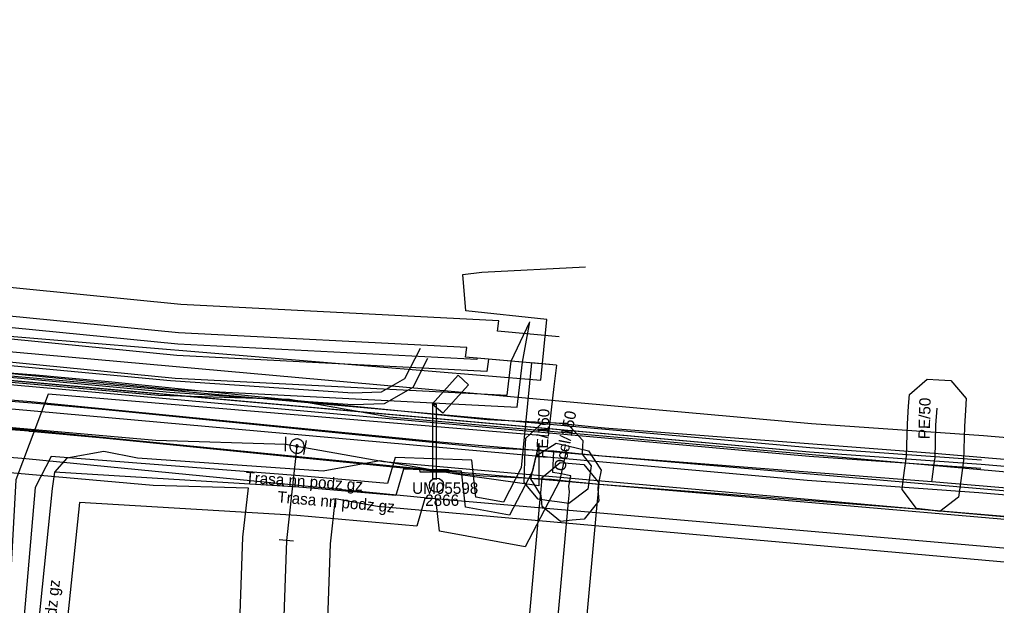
# Model space of a CAD drawing. Extents: x -762993 to -761845, y -975230 to -974501.
# Drawn here: x -762212.37 to -762178.08, y -975004.4 to -974983.83 of the extents above; entities that cross this region are included whole.
import ezdxf

# ---------------------------------------------------------------- set-up
doc = ezdxf.new("R2010")
doc.units = 0
for name, color, linetype in [('IS_CETIN_chranicka', 7, 'Continuous'), ('IS_CETIN_OP', 7, 'Continuous'), ('IS_CETIN_podzem optika zam', 7, 'Continuous'), ('IS_CEZ-D_anotace', 7, 'Continuous'), ('IS_CEZ-D_el vedeni NN podzem', 7, 'Continuous'), ('IS_CEZ-D_el vedeni VN podzem', 7, 'Continuous'), ('IS_CEZ-D_el vedeni VN podzem soubeh investice', 7, 'Continuous'), ('IS_CEZ-D_OP', 7, 'Continuous'), ('IS_CRA_podzem telekomunikace', 7, 'Continuous'), ('IS_DPmUL_OP', 7, 'Continuous'), ('IS_DPmUL_trakce anotace', 7, 'Continuous'), ('IS_DPmUL_trakce stozary', 7, 'Continuous'), ('IS_DPmUL_VO lampy', 7, 'Continuous'), ('IS_DPmUL_VO lampy anotace', 7, 'Continuous'), ('IS_DPmUL_VO vedeni podzem', 7, 'Continuous'), ('IS_GASNET_plyn NTL anotace', 7, 'Continuous'), ('IS_GASNET_plyn NTL pripojky', 7, 'Continuous'), ('IS_GASNET_plyn NTL rad', 7, 'Continuous'), ('IS_GASNET_plyn OP', 7, 'Continuous'), ('IS_SCVK_vodovod OP', 7, 'Continuous'), ('IS_SCVK_vodovod privadec', 7, 'Continuous'), ('IS_SCVK_vodovod znaky', 7, 'Continuous'), ('IS_TPS_podzem metalika', 7, 'Continuous')]:
    doc.layers.add(name, color=color, linetype=linetype)

msp = doc.modelspace()

# ---------------------------------------------------------------- linework, layer by layer
at = {"layer": 'IS_CETIN_chranicka'}
for points in [[(-762237.218, -974994.31), (-762217.891, -974995.882), (-762216.077, -974996.031), (-762184.637, -974998.851)], [(-762237.242, -974994.61), (-762217.915, -974996.182), (-762216.103, -974996.329), (-762184.663, -974999.149)], [(-762184.639, -974998.85), (-762178.609, -974999.28)], [(-762184.661, -974999.15), (-762178.631, -974999.58)]]:
    msp.add_lwpolyline(points, dxfattribs=at)
at = {"layer": 'IS_CETIN_OP'}
for points in [[(-762217.822, -974995.035), (-762216.005, -974995.184), (-762184.57, -974998.003), (-762178.542, -974998.433), (-762152.471, -975000.654), (-762131.203, -975002.624), (-762124.809, -975003.153), (-762118.93, -975003.623), (-762113.193, -975004.083), (-762107.364, -975004.514), (-762100.398, -975005.204), (-762087.589, -975006.295)], [(-762217.984, -974997.029), (-762216.175, -974997.176), (-762184.73, -974999.997), (-762178.698, -975000.427), (-762152.649, -975002.646), (-762131.377, -975004.616), (-762124.971, -975005.147), (-762119.09, -975005.617), (-762113.347, -975006.077), (-762107.536, -975006.506), (-762100.582, -975007.196), (-762087.759, -975008.287)]]:
    msp.add_lwpolyline(points, dxfattribs=at)
at = {"layer": 'IS_CETIN_podzem optika zam'}
msp.add_lwpolyline([(-762217.903, -974996.032), (-762216.09, -974996.18), (-762184.65, -974999), (-762178.62, -974999.43), (-762152.56, -975001.65), (-762131.29, -975003.62), (-762124.89, -975004.15), (-762119.01, -975004.62), (-762113.27, -975005.08), (-762107.45, -975005.51), (-762100.49, -975006.2), (-762087.674, -975007.291)], dxfattribs=at)
at = {"layer": 'IS_CEZ-D_el vedeni NN podzem'}
for points in [[(-762193.524, -974995.955), (-762195.916, -974995.748), (-762195.968, -974996.181), (-762206.85, -974995.622), (-762221.698, -974994.154), (-762246.209, -974992.883), (-762248.603, -974989.634), (-762249.046, -974987.054), (-762248.934, -974986.091), (-762247.847, -974984.536), (-762246.114, -974982.893)], [(-762193.524, -974995.955), (-762196.315, -974995.713), (-762196.321, -974995.763), (-762206.82, -974995.223), (-762221.661, -974993.755), (-762245.947, -974992.564), (-762248.224, -974989.473), (-762248.642, -974987.043), (-762248.543, -974986.191), (-762247.498, -974984.757), (-762245.839, -974983.184), (-762245.485, -974982.848), (-762245.111, -974983.239), (-762244.564, -974983.81), (-762244.131, -974983.395)], [(-762193.524, -974995.955), (-762196.714, -974995.678), (-762196.674, -974995.344), (-762206.79, -974994.824), (-762221.625, -974993.357), (-762245.684, -974992.246), (-762247.846, -974989.312), (-762248.238, -974987.032), (-762248.152, -974986.29), (-762247.149, -974984.977), (-762245.644, -974983.55), (-762245.499, -974983.413), (-762245.127, -974983.801), (-762244.853, -974984.087), (-762244.131, -974983.395)], [(-762193.524, -974995.956), (-762193.614, -974996.71), (-762193.822, -974998.453), (-762211.362, -974996.973), (-762212.503, -974999.99), (-762212.93, -975007.897), (-762212.59, -975008.699), (-762208.023, -975009.002), (-762208.841, -975020.191), (-762208.871, -975020.599), (-762216.194, -975020.151), (-762233.978, -975019.299), (-762252.877, -975017.917), (-762257.832, -975017.547), (-762262.774, -975017.178), (-762264.709, -975017.162), (-762266.642, -975017.146), (-762269.935, -975017.363)], [(-762193.524, -974995.955), (-762194.408, -974995.878), (-762194.761, -974999.565), (-762195.389, -975000.774), (-762196.355, -975000.599), (-762196.501, -974999.292), (-762199.187, -974999.2), (-762199.452, -975000.113), (-762202.537, -974999.841), (-762211.266, -974999.16), (-762211.822, -975000.258), (-762212.529, -975008.421)], [(-762194.15, -974998.7), (-762194.37, -974999.68), (-762195.17, -975001.22), (-762196.72, -975000.94), (-762196.86, -974999.68), (-762198.89, -974999.61), (-762199.16, -975000.54), (-762202.57, -975000.24), (-762211.14, -974999.72)], [(-762194.15, -974998.7), (-762194.15, -975000.19), (-762197.06, -974999.79), (-762199.73, -974999.32), (-762201.72, -974999.68), (-762208.23, -974999.23), (-762209.41, -974998.99), (-762210.71, -974999.22), (-762211.14, -974999.72)], [(-762211.14, -974999.72), (-762211.22, -975000.29), (-762212.06, -975008.46), (-762212.15, -975008.94), (-762212.14, -975010.58)]]:
    msp.add_lwpolyline(points, dxfattribs=at)
at = {"layer": 'IS_CEZ-D_el vedeni VN podzem'}
for points in [[(-762269.579, -974969.967), (-762269.216, -974971.463), (-762268.263, -974975.531), (-762267.512, -974976.705), (-762264.757, -974978.053), (-762262.777, -974978.189), (-762259.951, -974977.791), (-762257.059, -974975.091), (-762254.069, -974975.768), (-762249.558, -974980.329), (-762249.105, -974980.676), (-762247.006, -974982.026), (-762245.904, -974982.859), (-762247.37, -974986.49), (-762247.43, -974987.01), (-762247.09, -974988.99), (-762245.16, -974991.61), (-762241.64, -974993.28), (-762221.77, -974994.95), (-762206.91, -974996.42), (-762195.262, -974997.018), (-762195.119, -974995.819), (-762194.458, -974994.436)], [(-762269.605, -974971.556), (-762268.637, -974975.689), (-762267.788, -974977.015), (-762264.863, -974978.447), (-762262.763, -974978.591), (-762259.77, -974978.169), (-762256.941, -974975.528), (-762254.271, -974976.132), (-762249.823, -974980.63), (-762249.335, -974981.004), (-762247.235, -974982.354), (-762246.39, -974982.993), (-762247.761, -974986.39), (-762247.834, -974987.021), (-762247.468, -974989.151), (-762245.422, -974991.928), (-762241.746, -974993.673), (-762221.806, -974995.348), (-762206.94, -974996.819), (-762194.909, -974997.437), (-762194.72, -974995.856), (-762194.458, -974994.436)], [(-762245.09, -974982.81), (-762246.99, -974984.79), (-762247.4, -974985.77), (-762247.54, -974987.01), (-762247.5, -974988.33), (-762246.71, -974990.37), (-762245.42, -974991.69), (-762241.81, -974993.76), (-762241.12, -974993.94), (-762236.96, -974994.44), (-762231.73, -974994.71), (-762227.11, -974994.8), (-762224.15, -974995.55), (-762219.32, -974995.76), (-762207.1, -974996.91), (-762200.67, -974997.34), (-762199.56, -974997.3), (-762198.56, -974996.73), (-762198.04, -974995.71)]]:
    msp.add_lwpolyline(points, dxfattribs=at)
at = {"layer": 'IS_CEZ-D_el vedeni VN podzem soubeh investice'}
msp.add_lwpolyline([(-762198.314, -974995.373), (-762198.862, -974996.442), (-762199.673, -974996.904), (-762200.675, -974996.938), (-762207.068, -974996.511), (-762219.294, -974995.361), (-762224.092, -974995.152), (-762227.056, -974994.401), (-762231.716, -974994.31), (-762236.926, -974994.041), (-762241.03, -974993.548), (-762241.657, -974993.386), (-762245.172, -974991.371), (-762246.367, -974990.149), (-762247.098, -974988.261), (-762247.139, -974987.026), (-762247.003, -974985.858), (-762246.655, -974985.018), (-762244.801, -974983.086)], dxfattribs=at)
at = {"layer": 'IS_CEZ-D_OP'}
msp.add_line((-762210.265, -975000.775), (-762210.987, -975007.803), dxfattribs=at)
for points in [[(-762193.437, -974994.959), (-762195.598, -974994.771), (-762195.554, -974994.4), (-762206.715, -974993.827), (-762221.553, -974992.359), (-762243.371, -974991.352)], [(-762193.174, -974998.919), (-762193.423, -975000.026), (-762194.622, -975002.335), (-762197.632, -975001.792), (-762197.758, -975000.65), (-762198.147, -975000.636), (-762198.429, -975001.608), (-762202.644, -975001.237), (-762210.265, -975000.775)]]:
    msp.add_lwpolyline(points, dxfattribs=at)
at = {"layer": 'IS_CRA_podzem telekomunikace'}
msp.add_lwpolyline([(-762257.583, -974994.102), (-762251.601, -974995.42), (-762242.483, -974996.496), (-762240.634, -974996.224), (-762237.225, -974994.464), (-762216.085, -974996.188), (-762184.646, -974998.998), (-762178.626, -974999.438), (-762152.565, -975001.658), (-762131.295, -975003.618), (-762124.896, -975004.158), (-762119.016, -975004.628), (-762113.267, -975005.088), (-762107.455, -975005.508), (-762100.504, -975006.198), (-762086.855, -975007.364)], dxfattribs=at)
at = {"layer": 'IS_DPmUL_OP'}
msp.add_line((-762171.511, -975002.926), (-762197.933, -975000.64), dxfattribs=at)
for points in [[(-762197.743, -974998.649), (-762211.975, -974997.251), (-762222.816, -974996.361)], [(-762197.933, -975000.64), (-762212.155, -974999.243), (-762223.004, -974998.353)], [(-762171.339, -975000.934), (-762197.755, -974998.648)]]:
    msp.add_lwpolyline(points, dxfattribs=at)
at = {"layer": 'IS_DPmUL_trakce stozary'}
msp.add_circle((-762197.738, -975000.173), 0.25, dxfattribs=at)
at = {"layer": 'IS_DPmUL_VO lampy'}
for points in [[(-762196.981, -974996.314), (-762196.611, -974996.644), (-762197.511, -974997.644), (-762197.891, -974997.324)], [(-762197.871, -974997.324), (-762197.751, -974997.334), (-762197.751, -974999.974), (-762197.871, -974999.964)], [(-762198.321, -974999.624), (-762197.321, -974999.624), (-762197.321, -974999.714), (-762198.311, -974999.714)]]:
    msp.add_lwpolyline(points, close=True, dxfattribs=at)
at = {"layer": 'IS_DPmUL_VO vedeni podzem'}
for points in [[(-762197.841, -974999.644), (-762212.065, -974998.247), (-762222.898, -974997.358)], [(-762171.425, -975001.93), (-762197.841, -974999.644)]]:
    msp.add_lwpolyline(points, dxfattribs=at)
at = {"layer": 'IS_GASNET_plyn NTL pripojky'}
msp.add_lwpolyline([(-762180.35, -975000.05), (-762180.241, -974999.242), (-762180.24, -974999.23), (-762180.209, -974998.069), (-762180.17, -974997.47)], dxfattribs=at)
at = {"layer": 'IS_GASNET_plyn NTL rad'}
for points in [[(-762152.06, -975002.65), (-762164.37, -975001.57), (-762171.49, -975000.8), (-762180.35, -975000.05), (-762191.928, -974999.15), (-762192.87, -974999.06), (-762193.62, -974998.98), (-762196.019, -974998.86), (-762209.34, -974997.53), (-762211.92, -974997.29), (-762211.926, -974997.289), (-762215.99, -974996.98), (-762229.04, -974995.92), (-762230.6, -974995.81), (-762231.15, -974995.79), (-762234.191, -974995.47), (-762234.57, -974995.47)], [(-762193.36, -974999.77), (-762193.65, -974999.73), (-762193.62, -974998.98)], [(-762193.07, -975000.41), (-762193.09, -975000.21), (-762193.02, -974999.85), (-762193.36, -974999.77)], [(-762209.373, -975122.133), (-762207.18, -975102.52), (-762206.04, -975089.29), (-762203.68, -975062.33), (-762201.05, -975034.18), (-762200.13, -975024.62), (-762199.466, -975016.577), (-762194.51, -975016.37), (-762194.157, -975012.456), (-762193.646, -975006.792), (-762193.568, -975005.933), (-762193.101, -975000.758), (-762193.07, -975000.41)]]:
    msp.add_lwpolyline(points, dxfattribs=at)
at = {"layer": 'IS_GASNET_plyn OP'}
for points in [[(-762215.912, -974995.983), (-762211.806, -974996.295), (-762211.795, -974996.297), (-762209.244, -974996.535), (-762195.944, -974997.862), (-762193.542, -974997.983), (-762192.769, -974998.065), (-762191.842, -974998.154), (-762180.269, -974999.053), (-762171.394, -974999.805), (-762164.273, -975000.575), (-762151.966, -975001.654)], [(-762152.154, -975003.646), (-762164.467, -975002.565), (-762171.586, -975001.795), (-762180.431, -975001.047), (-762192.014, -975000.146), (-762192.971, -975000.055), (-762193.698, -974999.977), (-762196.094, -974999.858), (-762209.436, -974998.525), (-762212.002, -974998.286), (-762212.024, -974998.284), (-762212.049, -974998.282), (-762216.068, -974997.977)], [(-762194.564, -975005.843), (-762194.097, -975000.669), (-762194.066, -975000.321), (-762194.029, -974999.908), (-762193.394, -974999.377), (-762192.981, -974999.414), (-762192.568, -974999.451), (-762192.037, -975000.086), (-762192.074, -975000.499), (-762192.105, -975000.847), (-762192.572, -975006.023)]]:
    msp.add_lwpolyline(points, dxfattribs=at)
for points in [[(-762181.396, -975000.327), (-762181.341, -974999.917), (-762181.238, -974999.15), (-762181.209, -974998.024), (-762181.168, -974997.403), (-762181.14, -974996.99), (-762180.516, -974996.445), (-762180.103, -974996.472), (-762179.69, -974996.5), (-762179.145, -974997.124), (-762179.172, -974997.537), (-762179.211, -974998.116), (-762179.242, -974999.31), (-762179.359, -975000.183), (-762179.414, -975000.593), (-762180.073, -975001.096), (-762180.483, -975001.041), (-762180.893, -975000.986)], [(-762192.621, -974999.02), (-762192.624, -974999.086), (-762192.313, -974999.497), (-762192.369, -974999.907), (-762192.426, -975000.317), (-762193.087, -975000.817), (-762193.497, -975000.761), (-762193.787, -975000.721), (-762194.169, -975000.668), (-762194.664, -975000.076), (-762194.649, -974999.69), (-762194.619, -974998.94), (-762194.602, -974998.526), (-762193.994, -974997.964), (-762193.58, -974997.981), (-762193.166, -974997.998), (-762192.604, -974998.606)], [(-762194.024, -975000.922), (-762194.063, -975000.534), (-762194.428, -974999.944), (-762194.333, -974999.541), (-762194.238, -974999.138), (-762193.534, -974998.702), (-762193.131, -974998.797), (-762192.791, -974998.877), (-762192.399, -974998.969), (-762191.961, -974999.646), (-762192.038, -975000.041), (-762192.08, -975000.257), (-762192.075, -975000.31), (-762192.034, -975000.723), (-762192.558, -975001.364), (-762192.97, -975001.405), (-762193.383, -975001.446)]]:
    msp.add_lwpolyline(points, close=True, dxfattribs=at)
at = {"layer": 'IS_SCVK_vodovod OP'}
for p, q in [((-762204.349, -975000.269), (-762204.543, -975002.001)), ((-762201.291, -975000.645), (-762201.469, -975002.227))]:
    msp.add_line(p, q, dxfattribs=at)
for points in [[(-762257.658, -974992.58), (-762207.497, -974997.012), (-762202.898, -974997.152)], [(-762257.936, -974995.728), (-762207.685, -975000.168), (-762204.349, -975000.269)], [(-762202.898, -974997.152), (-762199.388, -974997.773), (-762175.758, -974999.875), (-762175.129, -974999.903), (-762163.968, -975000.821)], [(-762201.291, -975000.645), (-762199.804, -975000.909), (-762175.968, -975003.029), (-762175.329, -975003.057), (-762164.228, -975003.971)], [(-762204.543, -975002.001), (-762206.54, -975058.879), (-762207.836, -975077.307)], [(-762201.469, -975002.227), (-762203.464, -975059.041), (-762204.764, -975077.523)]]:
    msp.add_lwpolyline(points, dxfattribs=at)
at = {"layer": 'IS_SCVK_vodovod privadec'}
for points in [[(-762257.797, -974994.154), (-762207.591, -974998.59), (-762203.041, -974998.728)], [(-762202.634, -974998.8), (-762203.006, -975002.114)], [(-762202.357, -974998.852), (-762199.596, -974999.341), (-762175.863, -975001.452), (-762175.229, -975001.48), (-762164.098, -975002.396)], [(-762203.006, -975002.114), (-762205.002, -975058.96), (-762206.3, -975077.415)]]:
    msp.add_lwpolyline(points, dxfattribs=at)
at = {"layer": 'IS_SCVK_vodovod znaky'}
for points in [[(-762203.034, -974998.478), (-762203.049, -974998.978)], [(-762203.041, -974998.728), (-762202.634, -974998.8)], [(-762202.388, -974998.843), (-762202.385, -974998.817), (-762202.384, -974998.791), (-762202.387, -974998.765), (-762202.391, -974998.74), (-762202.399, -974998.714), (-762202.41, -974998.69), (-762202.422, -974998.668), (-762202.437, -974998.646), (-762202.454, -974998.626), (-762202.473, -974998.608), (-762202.495, -974998.592), (-762202.517, -974998.579), (-762202.541, -974998.568), (-762202.565, -974998.56), (-762202.591, -974998.554), (-762202.617, -974998.551), (-762202.643, -974998.55), (-762202.669, -974998.552), (-762202.694, -974998.557), (-762202.72, -974998.565), (-762202.743, -974998.576), (-762202.767, -974998.588), (-762202.788, -974998.603), (-762202.808, -974998.62), (-762202.826, -974998.639), (-762202.841, -974998.66), (-762202.855, -974998.683), (-762202.866, -974998.707), (-762202.874, -974998.731), (-762202.88, -974998.757), (-762202.883, -974998.783), (-762202.883, -974998.809), (-762202.882, -974998.835), (-762202.877, -974998.86), (-762202.868, -974998.886), (-762202.859, -974998.91), (-762202.846, -974998.932), (-762202.831, -974998.954), (-762202.814, -974998.974), (-762202.795, -974998.992), (-762202.773, -974999.008), (-762202.751, -974999.021), (-762202.727, -974999.032), (-762202.703, -974999.04), (-762202.677, -974999.046), (-762202.651, -974999.049), (-762202.625, -974999.05), (-762202.599, -974999.048), (-762202.574, -974999.043), (-762202.548, -974999.035), (-762202.524, -974999.025), (-762202.502, -974999.012), (-762202.48, -974998.997), (-762202.46, -974998.98), (-762202.442, -974998.961), (-762202.426, -974998.939), (-762202.413, -974998.917), (-762202.402, -974998.893), (-762202.394, -974998.869), (-762202.388, -974998.843)], [(-762202.594, -974998.807), (-762202.593, -974998.802), (-762202.593, -974998.799), (-762202.593, -974998.794), (-762202.594, -974998.79), (-762202.595, -974998.785), (-762202.597, -974998.782), (-762202.599, -974998.778), (-762202.601, -974998.775), (-762202.605, -974998.772), (-762202.608, -974998.769), (-762202.611, -974998.766), (-762202.615, -974998.764), (-762202.618, -974998.762), (-762202.622, -974998.76), (-762202.627, -974998.76), (-762202.631, -974998.758), (-762202.635, -974998.759), (-762202.64, -974998.759), (-762202.644, -974998.76), (-762202.648, -974998.761), (-762202.652, -974998.763), (-762202.655, -974998.765), (-762202.659, -974998.768), (-762202.663, -974998.771), (-762202.665, -974998.774), (-762202.668, -974998.777), (-762202.67, -974998.78), (-762202.672, -974998.785), (-762202.674, -974998.788), (-762202.674, -974998.793), (-762202.675, -974998.797), (-762202.675, -974998.801), (-762202.675, -974998.806), (-762202.674, -974998.81), (-762202.672, -974998.814), (-762202.671, -974998.818), (-762202.669, -974998.822), (-762202.666, -974998.825), (-762202.663, -974998.829), (-762202.66, -974998.831), (-762202.657, -974998.834), (-762202.653, -974998.836), (-762202.649, -974998.838), (-762202.645, -974998.84), (-762202.641, -974998.84), (-762202.637, -974998.841), (-762202.633, -974998.841), (-762202.628, -974998.841), (-762202.624, -974998.84), (-762202.62, -974998.839), (-762202.616, -974998.837), (-762202.612, -974998.834), (-762202.609, -974998.832), (-762202.606, -974998.829), (-762202.603, -974998.826), (-762202.6, -974998.823), (-762202.598, -974998.819), (-762202.596, -974998.815), (-762202.594, -974998.812), (-762202.594, -974998.807)], [(-762202.634, -974998.8), (-762202.357, -974998.852)], [(-762202.311, -974998.606), (-762202.404, -974999.098)], [(-762202.758, -975002.142), (-762203.254, -975002.086)]]:
    msp.add_lwpolyline(points, dxfattribs=at)
at = {"layer": 'IS_TPS_podzem metalika'}
msp.add_lwpolyline([(-762240.486, -974977.956), (-762246.238, -974984.004), (-762246.978, -974984.75), (-762247.396, -974985.793), (-762247.518, -974986.973), (-762247.497, -974988.28), (-762246.746, -974990.312), (-762245.354, -974991.693), (-762243.76, -974992.38), (-762227.7, -974993.7), (-762194.072, -974996.484), (-762193.869, -974994.354), (-762196.707, -974994.049), (-762196.809, -974992.782), (-762196.146, -974992.699), (-762192.513, -974992.502)], dxfattribs=at)

# ---------------------------------------------------------------- texts
at = {"layer": 'IS_CEZ-D_anotace'}
for rotation, p in [(356.0458, (-762204.455, -975000.092)), (354.9723, (-762203.336, -975000.775)), (84.1298, (-762211.371, -975007.621))]:
    msp.add_text('Trasa nn podz gz', height=0.4, rotation=rotation, dxfattribs=at).set_placement(p)
at = {"layer": 'IS_DPmUL_trakce anotace'}
msp.add_text('2866', height=0.4, dxfattribs=at).set_placement((-762198.133, -975000.899))
at = {"layer": 'IS_DPmUL_VO lampy anotace'}
msp.add_text('UM05598', height=0.4, dxfattribs=at).set_placement((-762198.591, -975000.477))
at = {"layer": 'IS_GASNET_plyn NTL anotace'}
for s, rotation, p in [('PE/50', 88.4705, (-762180.428, -974998.563)), ('PE/160', 87.7094, (-762193.839, -974999.251)), ('Ocel/150', 78.9965, (-762193.231, -974999.708))]:
    msp.add_text(s, height=0.4, rotation=rotation, dxfattribs=at).set_placement(p)

doc.saveas('drawing.dxf')
